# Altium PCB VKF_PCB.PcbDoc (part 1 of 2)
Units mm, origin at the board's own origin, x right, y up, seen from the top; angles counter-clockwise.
Board outline 125 x 80 mm, 4 copper layers (Top Layer, Mid-Layer 1, Mid-Layer 2, Bottom Layer), stack 1.633 mm thick; 104 components, 58 nets, 332 pads, 515 vias.
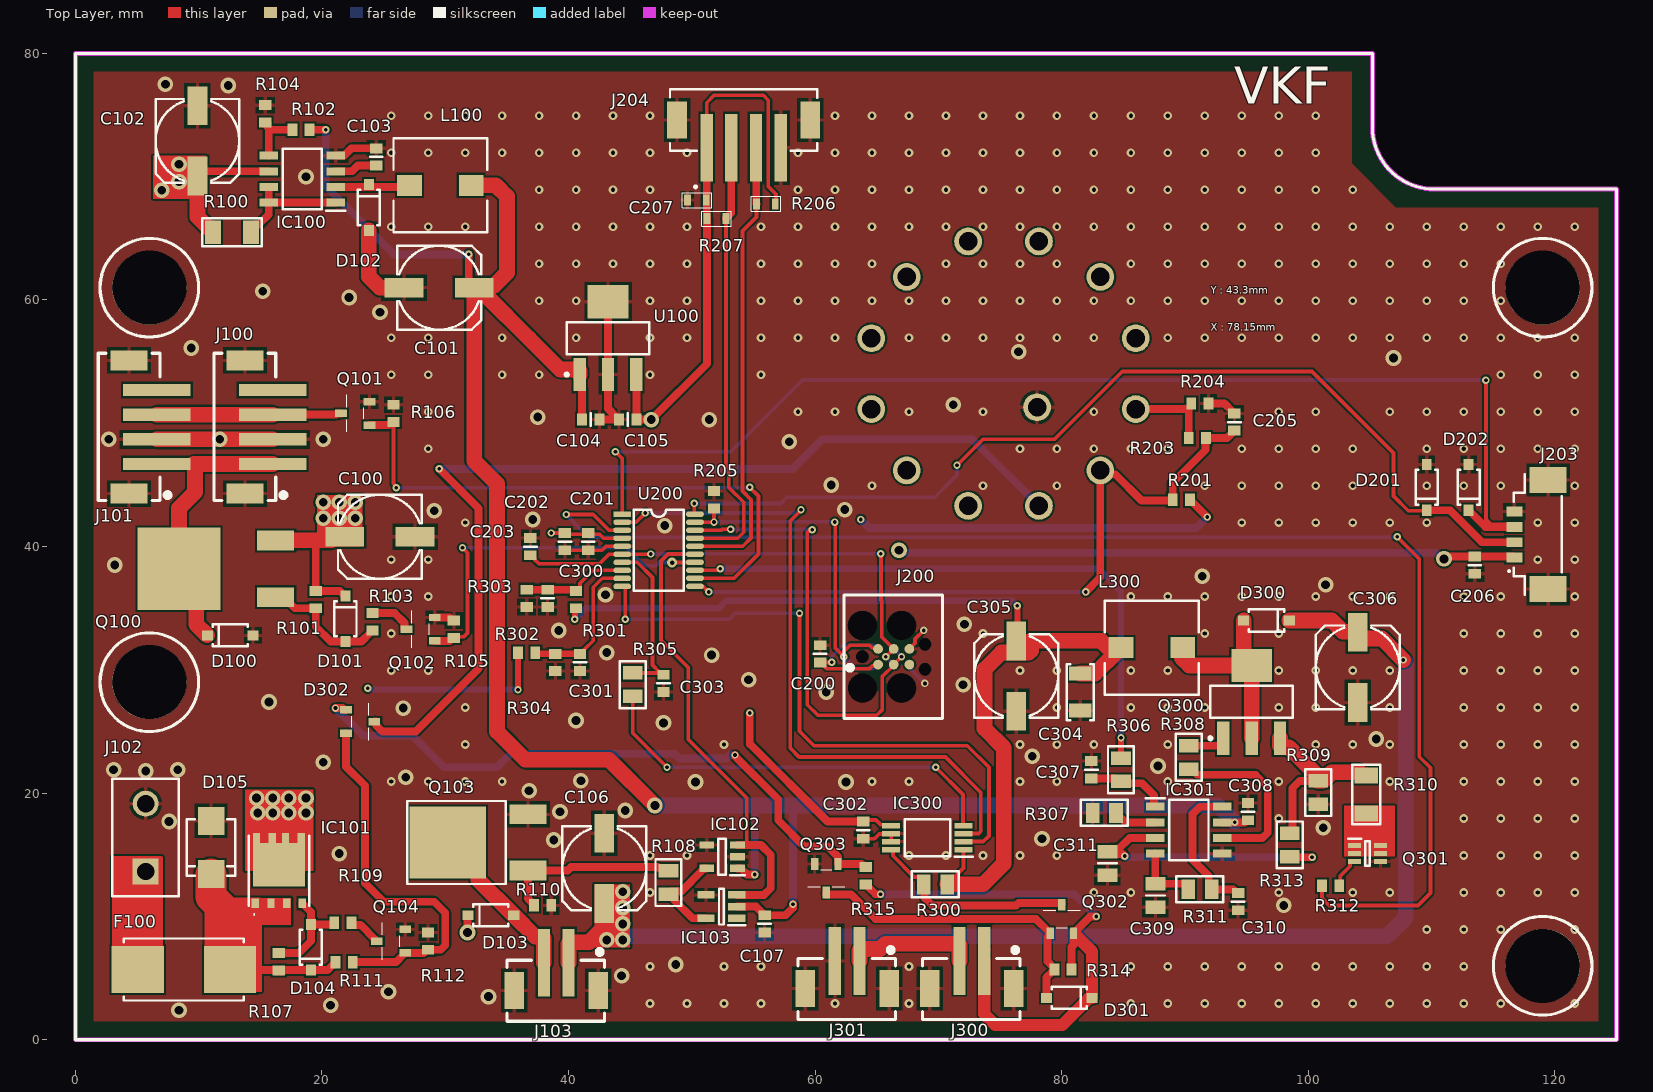
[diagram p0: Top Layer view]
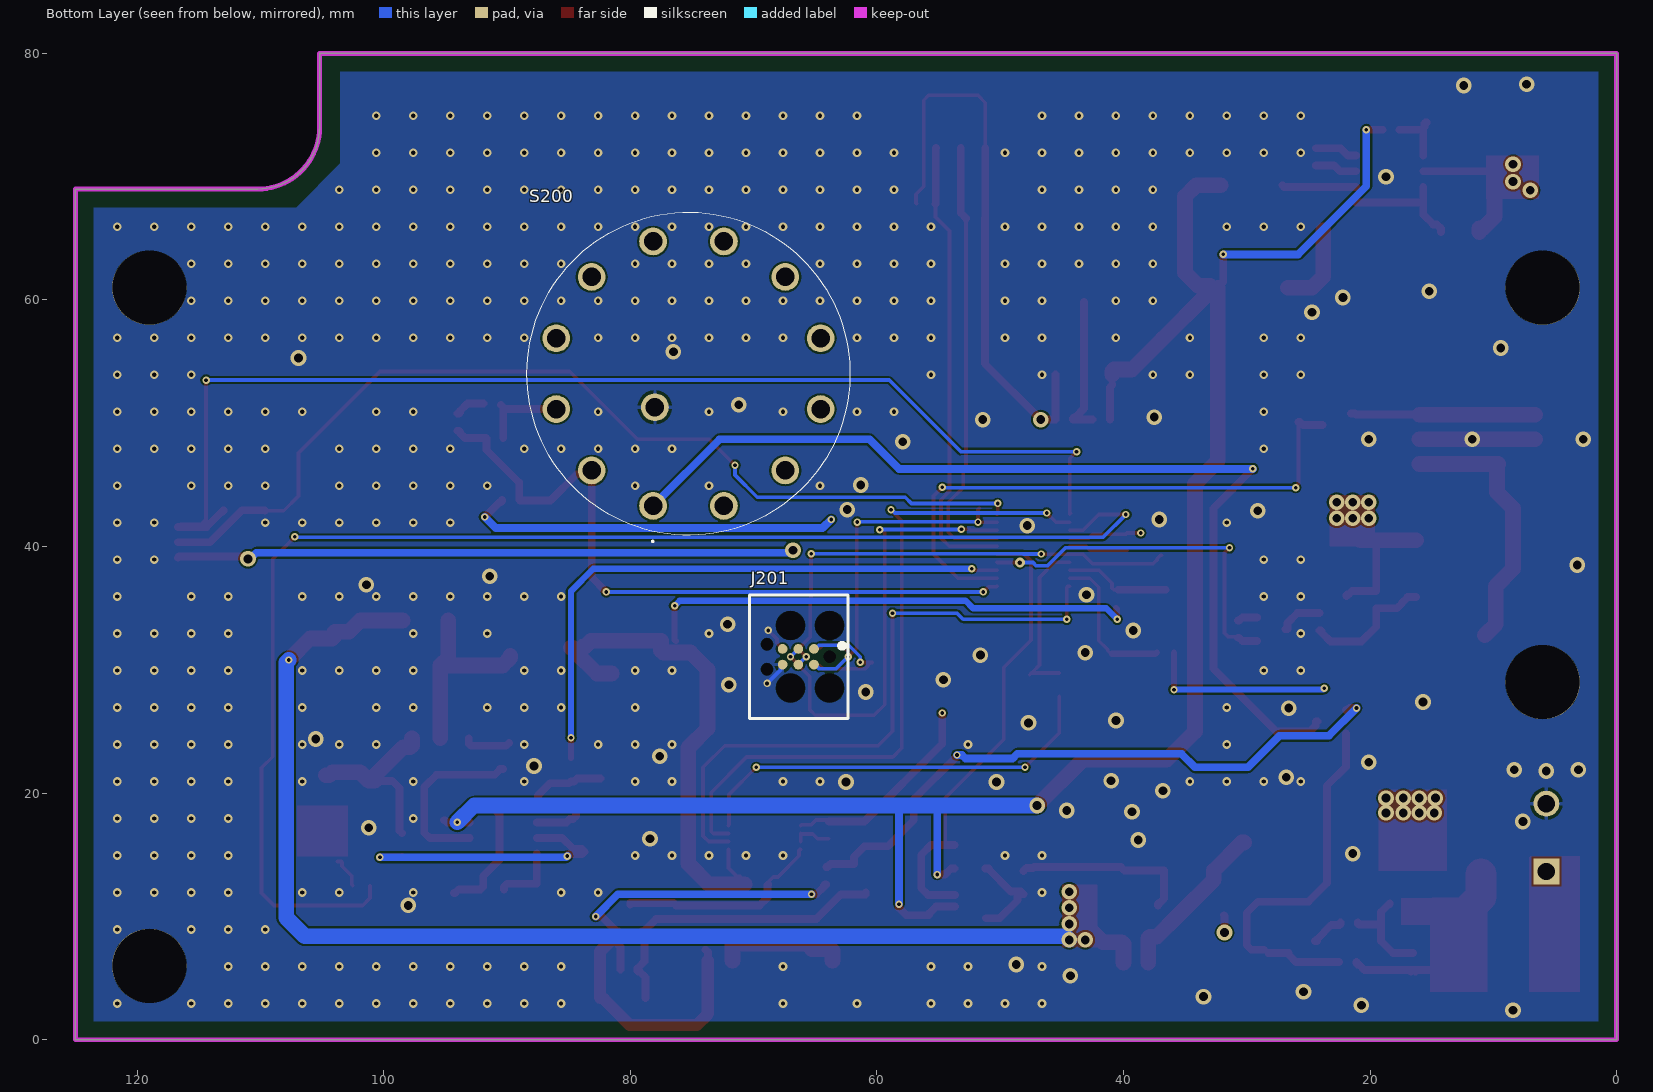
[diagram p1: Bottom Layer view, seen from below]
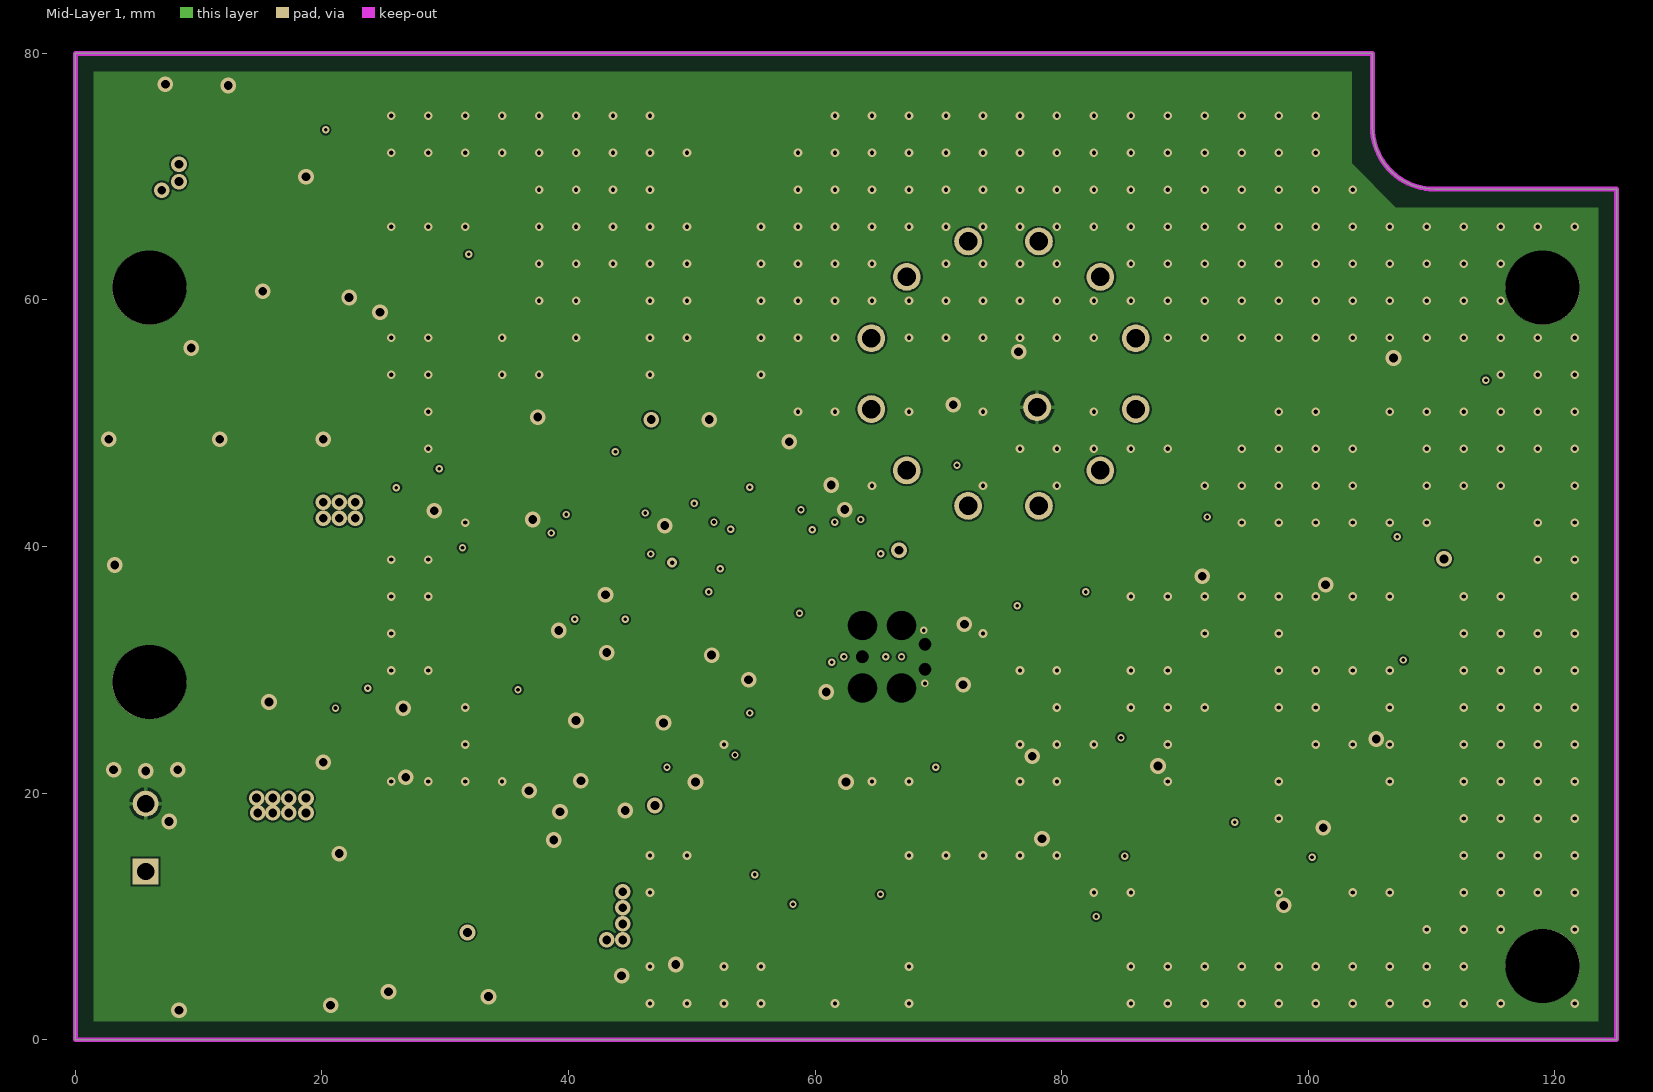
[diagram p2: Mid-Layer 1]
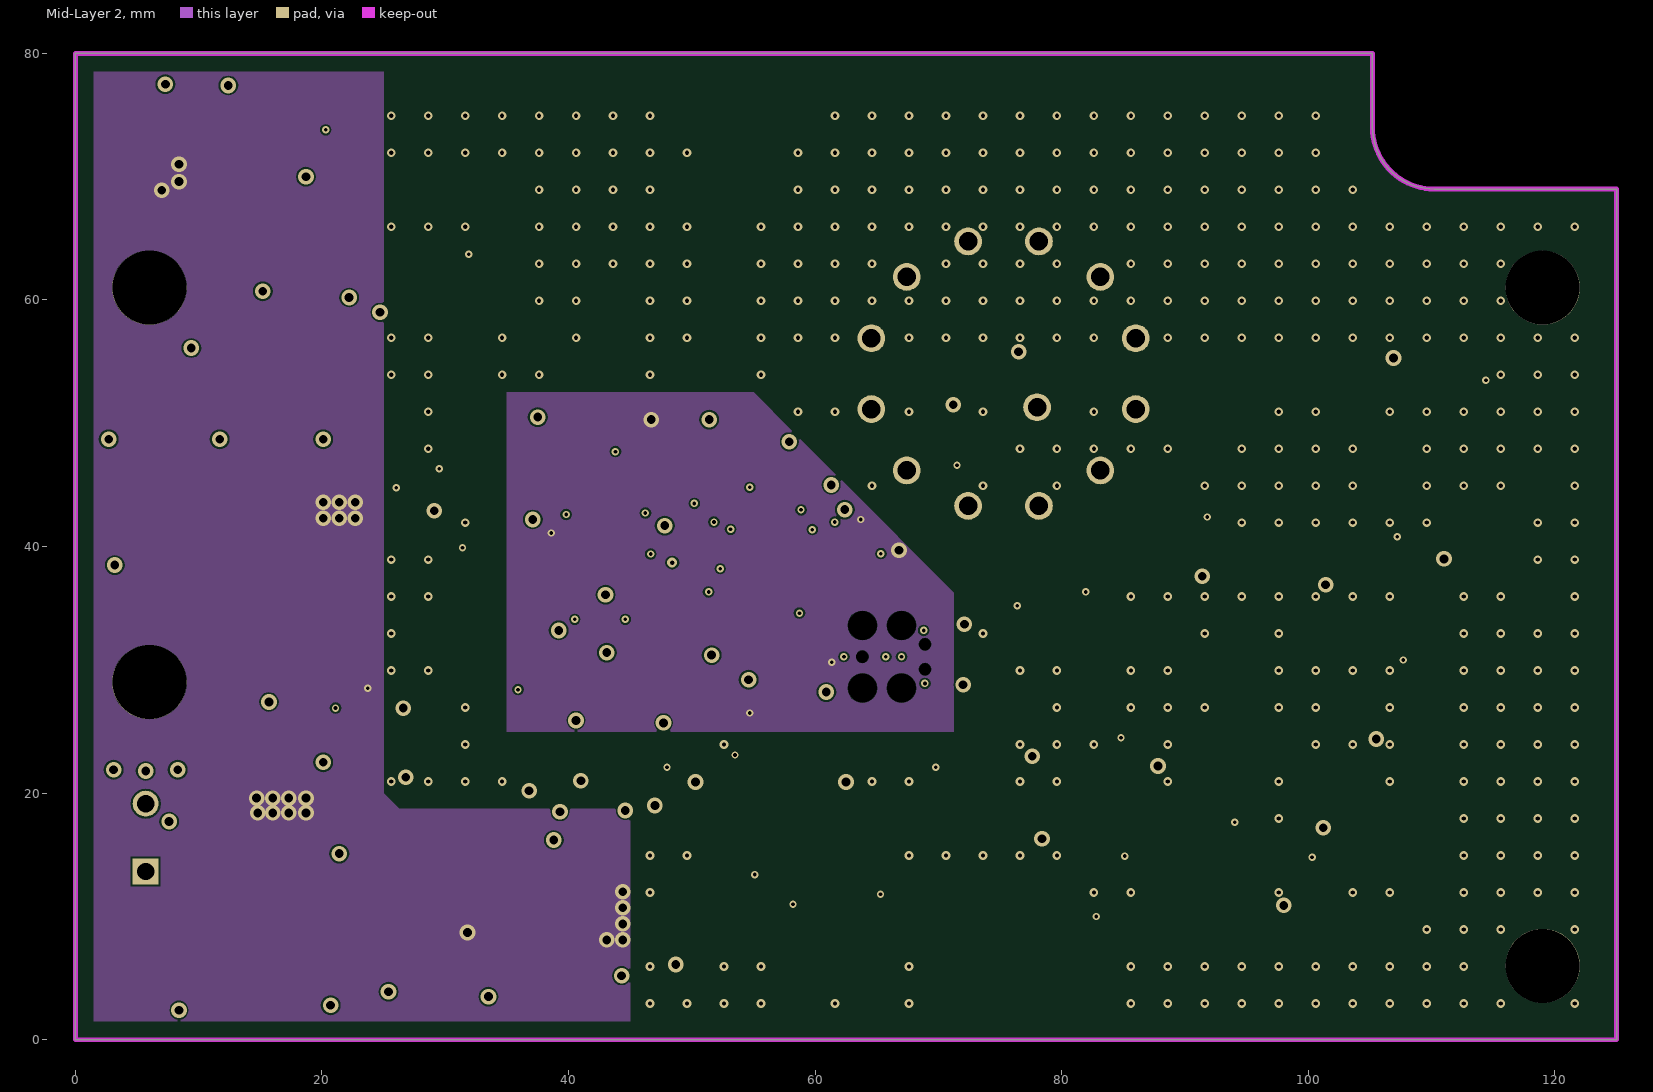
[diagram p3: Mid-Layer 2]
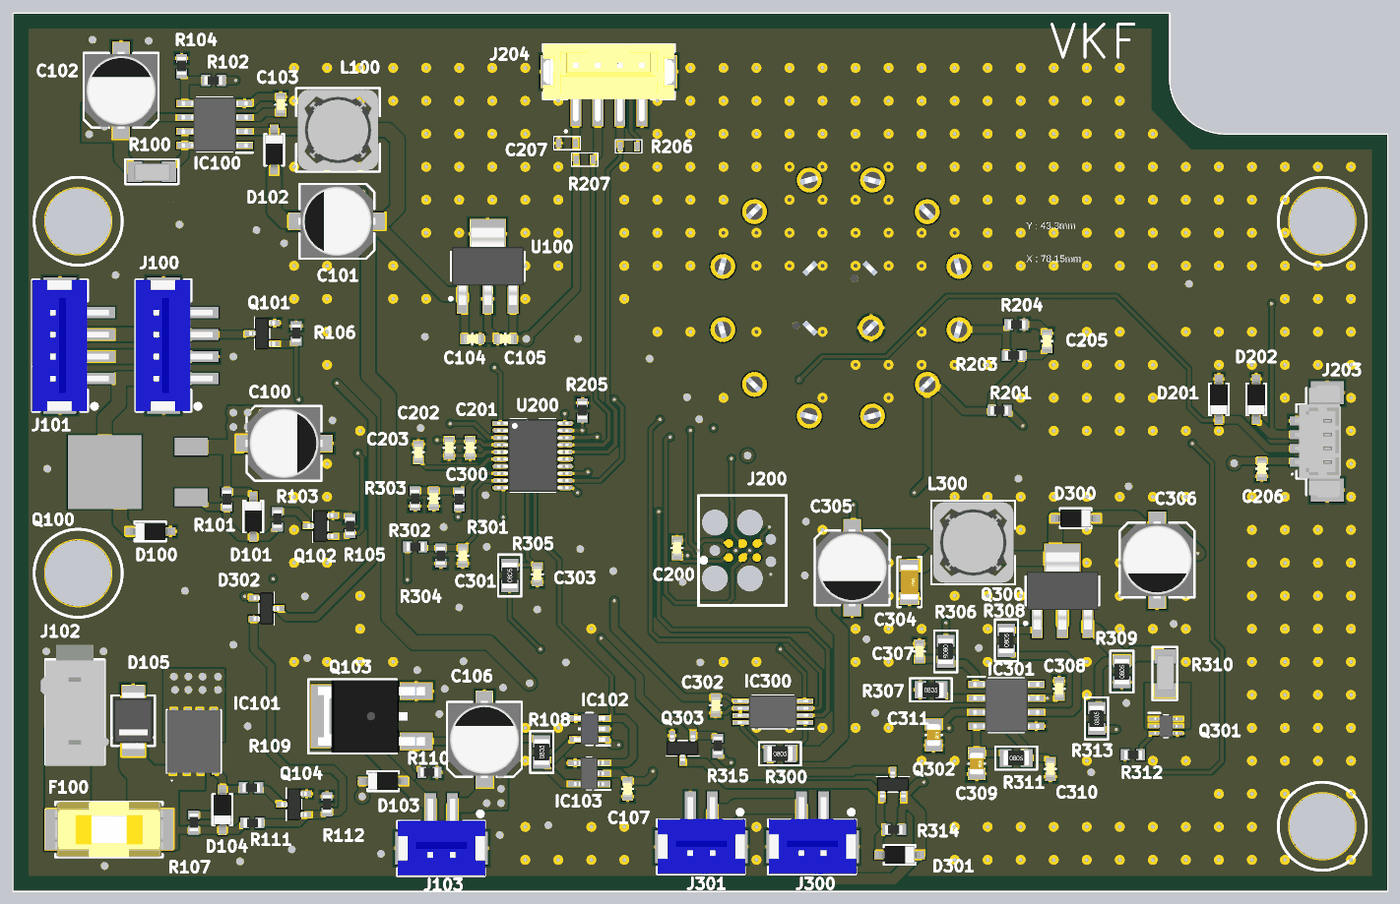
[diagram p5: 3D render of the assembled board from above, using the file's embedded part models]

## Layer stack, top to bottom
Top Solder: solder mask 0.001, Solder Resist, Dk 3.5
Top Layer: signal copper 0.035
Dielectric1: core 0.7, FR-4, Dk 4.8
Mid-Layer 1: signal copper 0.018
Dielectric 3: dielectric 0.127, Polyamide, Dk 3.2
Mid-Layer 2: signal copper 0.018
Dielectric2: core 0.7, FR-4, Dk 4.2
Bottom Layer: signal copper 0.035
Bottom Solder: solder mask 0.01, Solder Resist, Dk 3.5

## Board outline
0,0 125,0 125,69 110.2,69 cw(c110.2,74) 105.2,74 105.2,80 0,80

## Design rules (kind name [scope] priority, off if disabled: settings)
Clearance Clearance_Trous_All [HasPad('Free-Trou' )] p1: gap=0.5 ignorepadtopadclearanceinfootprint=FALSE except(0: Arc-Hole Track-Hole SMDPad-Hole THPad-Hole Via-Hole Fill-Hole Poly-Hole Region-Hole Text-Hole)
Clearance Clearance_Via_Pads [IsVia vs IsPad] p2: gap=0.2 ignorepadtopadclearanceinfootprint=FALSE except(0: Arc-Hole Track-Hole SMDPad-Hole THPad-Hole Via-Hole Fill-Hole Poly-Hole Region-Hole Text-Hole; 0.3: Track-Poly SMDPad-Poly THPad-Poly Via-Poly Fill-Poly Poly-Poly)
Clearance Clearance_KOL_Pad [(IsTrack Or IsArc) And OnLayer('Keep-out Layer' ) vs IsPad] p3: gap=0.6 ignorepadtopadclearanceinfootprint=FALSE except(0: Arc-Hole Track-Hole SMDPad-Hole THPad-Hole Via-Hole Fill-Hole Poly-Hole Region-Hole Text-Hole)
Clearance Clearance_KOL_Via [(IsTrack Or IsArc) And OnLayer('Keep-out Layer' ) vs IsVia] p4: gap=0.25 ignorepadtopadclearanceinfootprint=FALSE except(0: Arc-Hole Track-Hole SMDPad-Hole THPad-Hole Via-Hole Fill-Hole Poly-Hole Region-Hole Text-Hole)
Clearance Clearance_KOL_All [(IsTrack Or IsArc) And OnLayer('Keep-out Layer' )] p5: gap=0.15 ignorepadtopadclearanceinfootprint=FALSE except(0: Arc-Hole Track-Hole SMDPad-Hole THPad-Hole Via-Hole Fill-Hole Poly-Hole Region-Hole Text-Hole)
Clearance Clearance_Fiduciales [HasPad('Free-f')] p6: gap=0.5 ignorepadtopadclearanceinfootprint=FALSE except(0: Arc-Hole Track-Hole SMDPad-Hole THPad-Hole Via-Hole Fill-Hole Poly-Hole Region-Hole Text-Hole)
Clearance Clearance_All_Power [All vs InNet('GND_MECA')] p7: gap=0.5 ignorepadtopadclearanceinfootprint=FALSE except(0: Arc-Hole Track-Hole SMDPad-Hole THPad-Hole Via-Hole Fill-Hole Poly-Hole Region-Hole Text-Hole)
Clearance "Clearance All" [All] p8: gap=0.15 ignorepadtopadclearanceinfootprint=FALSE except(0: Arc-Hole Track-Hole SMDPad-Hole THPad-Hole Via-Hole Fill-Hole Poly-Hole Region-Hole Text-Hole)
ComponentClearance [All] p1: gap=0.6 collisioncheckmode=3 verticalgap=0.254 showdistances=FALSE
DiffPairsRouting [All] p1: maxlimit=3 minlimit=0.15 mostfreqgap=0.2 substack1={CD9D98E9-E3DC-47B0-9C38-DEE56D303F75} toplayer_{cd9d98e9-e3dc-47b0-9c38-dee56d303f75}_minwidth=0.381 toplayer_{cd9d98e9-e3dc-47b0-9c38-dee56d303f75}_maxwidth=0.381 toplayer_{cd9d98e9-e3dc-47b0-9c38-dee56d303f75}_prefwidth=0.381 midlayer1_{cd9d98e9-e3dc-47b0-9c38-dee56d303f75}_minwidth=0.381 midlayer1_{cd9d98e9-e3dc-47b0-9c38-dee56d303f75}_maxwidth=0.381 midlayer1_{cd9d98e9-e3dc-47b0-9c38-dee56d303f75}_prefwidth=0.381 midlayer2_{cd9d98e9-e3dc-47b0-9c38-dee56d303f75}_minwidth=0.381 midlayer2_{cd9d98e9-e3dc-47b0-9c38-dee56d303f75}_maxwidth=0.381 midlayer2_{cd9d98e9-e3dc-47b0-9c38-dee56d303f75}_prefwidth=0.381 bottomlayer_{cd9d98e9-e3dc-47b0-9c38-dee56d303f75}_minwidth=0.381 bottomlayer_{cd9d98e9-e3dc-47b0-9c38-dee56d303f75}_maxwidth=0.381 bottomlayer_{cd9d98e9-e3dc-47b0-9c38-dee56d303f75}_prefwidth=0.381 toplayer_minwidth=0.381 toplayer_maxwidth=0.381 toplayer_prefwidth=0.381 midlayer1_minwidth=0.381 midlayer1_maxwidth=0.381 midlayer1_prefwidth=0.381 midlayer2_minwidth=0.381 midlayer2_maxwidth=0.381 midlayer2_prefwidth=0.381 bottomlayer_minwidth=0.381 bottomlayer_maxwidth=0.381 bottomlayer_prefwidth=0.381 substack2={AC1A69B8-2080-43DA-BC4E-ABC400F5E514} toplayer_{ac1a69b8-2080-43da-bc4e-abc400f5e514}_minwidth=0.381 toplayer_{ac1a69b8-2080-43da-bc4e-abc400f5e514}_maxwidth=0.381 toplayer_{ac1a69b8-2080-43da-bc4e-abc400f5e514}_prefwidth=0.381 midlayer1_{ac1a69b8-2080-43da-bc4e-abc400f5e514}_minwidth=0.381 midlayer1_{ac1a69b8-2080-43da-bc4e-abc400f5e514}_maxwidth=0.381 midlayer1_{ac1a69b8-2080-43da-bc4e-abc400f5e514}_prefwidth=0.381 midlayer2_{ac1a69b8-2080-43da-bc4e-abc400f5e514}_minwidth=0.381 midlayer2_{ac1a69b8-2080-43da-bc4e-abc400f5e514}_maxwidth=0.381 midlayer2_{ac1a69b8-2080-43da-bc4e-abc400f5e514}_prefwidth=0.381 bottomlayer_{ac1a69b8-2080-43da-bc4e-abc400f5e514}_minwidth=0.381 bottomlayer_{ac1a69b8-2080-43da-bc4e-abc400f5e514}_maxwidth=0.381 bottomlayer_{ac1a69b8-2080-43da-bc4e-abc400f5e514}_prefwidth=0.381 maxuncoupledlength=12.7
FabricationTestPointUsage [All] p1: valid=0 allowmultiple=TRUE
FabricationTestpoint [All] p1: side=3 testpointundercomponent=TRUE minsize=1 maxsize=4 preferedsize=1 minholesize=0 maxholesize=2 preferedholesize=0.4 testpointgrid=0.025 allowsidetop=TRUE allowsidebottom=TRUE usegrid=FALSE gridtolerance=0
Height [All] p1: minheight=0 maxheight=50 prefheight=12.7
HoleSize [All] p1: absolutevalues=TRUE maxlimit=8 minlimit=0.3 maxpercent=80.000 minpercent=20.000
MinimumAnnularRing [IsPad] p1: minimumring=0.15
MinimumAnnularRing MinimumAnnularRing_Via [IsVia] p2: minimumring=0.15
MinimumSolderMaskSliver [All] p1: minsoldermaskwidth=0
PasteMaskExpansion [All] p1: expansion=-0.05
PlaneClearance [All] p1: clearance=0.5
PlaneConnect [All] p1: planeconnectstyle=Relief reliefexpansion=0.3 reliefentries=4 reliefconductorwidth=0.3 reliefairgap=0.3
PolygonConnect "PolygonConnect_Free Trous" [HasPad('Free-Trou' )] p1: connectstyle=Direct reliefconductorwidth=0.254 reliefentries=4 polygonreliefangle="90 Angle" airgapwidth=0.254
PolygonConnect PolygonConnect_Vias [IsVia] p2: connectstyle=Direct reliefconductorwidth=0.254 reliefentries=4 polygonreliefangle="90 Angle" airgapwidth=0.254
PolygonConnect PolygonConnect_Power [InNet('GND_MECA') Or InNet('VBAT')] p3: connectstyle=Relief reliefconductorwidth=1 reliefentries=4 polygonreliefangle="90 Angle" airgapwidth=0.254
PolygonConnect PolygonConnect_Power_1 [InNet('GND_MECA') Or InNet('VBAT')] p4 off: connectstyle=Relief reliefconductorwidth=0.5 reliefentries=4 polygonreliefangle="90 Angle" airgapwidth=0.254
PolygonConnect PolygonConnect_GND [InNet('GND')] p5: connectstyle=Relief reliefconductorwidth=0.3 reliefentries=4 polygonreliefangle="90 Angle" airgapwidth=0.254
PolygonConnect PolygonConnect_GND_1 [InNet('GND')] p6 off: connectstyle=Relief reliefconductorwidth=0.3 reliefentries=4 polygonreliefangle="90 Angle" airgapwidth=0.254
PolygonConnect PolygonConnect_All [All] p7: connectstyle=Relief reliefconductorwidth=0.3 reliefentries=4 polygonreliefangle="90 Angle" airgapwidth=0.254
RoutingCorners [All] p1: cornerstyle=45-Degree minsetback=1 maxsetback=3
RoutingVias [All] p1: holewidth=0.35 width=0.8 viastyle="Through Hole" minholewidth=0.3 minwidth=0.6 maxholewidth=1.5 maxwidth=2.8
SilkToSilkClearance [All] p1 off: silktosilkclearance=0.6
SilkToSolderMaskClearance SilkscreenOverComponentPads [IsPad] p1 off: minsilkscreentomaskgap=0 clearancetoexposedcopper=TRUE
SolderMaskExpansion SolderMaskExpansion_Via [(IsVia)] p1: expansion=0 istentingtop=FALSE
SolderMaskExpansion [All] p2: expansion=0.1 istentingtop=FALSE
Width Alim [InNet('15V') Or InNet('15V1') Or InNet('15V2') Or InNet('5V') Or InNet('5V1') Or InNet('5V2') Or InNet('GND') Or InNet('3.3V') Or InNet('12V')] p1: maxlimit=5 minlimit=0.15 preferedwidth=0.3 substack1={CD9D98E9-E3DC-47B0-9C38-DEE56D303F75} substack2={AC1A69B8-2080-43DA-BC4E-ABC400F5E514}
Width Power [InNet('GND_MECA') Or InNet('VBAT')] p2: maxlimit=5 minlimit=0.15 preferedwidth=1.5 substack1={CD9D98E9-E3DC-47B0-9C38-DEE56D303F75} substack2={AC1A69B8-2080-43DA-BC4E-ABC400F5E514}
Width All [All] p3: maxlimit=3 minlimit=0.15 preferedwidth=0.2 substack1={CD9D98E9-E3DC-47B0-9C38-DEE56D303F75} substack2={AC1A69B8-2080-43DA-BC4E-ABC400F5E514}
17 further rules are at their usual default settings.

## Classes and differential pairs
component class VKF_SOLAIRE: C300 C301 C302 C303 C304 C305 C306 C307 C308 C309 C310 C311 D300 D301 D302 IC300 IC301 J300 J301 L300 Q300 Q301 Q302 Q303 R300 R301 R302 R303 R304 R305 R306 R307 R308 R309 R310 R311 R312 R313 R314 R315
component class VKF_ALIM: C100 C101 C102 C103 C104 C105 C106 C107 D100 D101 D102 D103 D104 D105 F100 IC100 IC101 IC102 IC103 J100 J101 J102 J103 L100 Q100 Q101 Q102 Q103 Q104 R100 R101 R102 R103 R104 R105 R106 R107 R108 R109 R110 R111 R112 U100
component class VKF_CPU: C200 C201 C202 C203 C205 C206 C207 D201 D202 J200 J201 J203 J204 R201 R203 R204 R205 R206 R207 S200 U200

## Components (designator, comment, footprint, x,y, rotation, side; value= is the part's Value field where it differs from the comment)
C100 "100µF" CP_D8 24.7,40.8 r0 top
C101 "220µF" CP_D8 29.5,61 r180 top
C102 "100µF" CP_D8 9.9,72.9 r90 top
C103 "470pF" CAP0603 24.4,71.6 r90 top
C104 "1µF" CAP0603 41.8,50.3 r0 top
C105 "2.2µF" CAP0603 44.8,50.3 r180 top
C106 "100µF" CP_D8 42.9,13.9 r90 top
C107 "100nF" CAP0603 55.9,9.4 r270 top
C200 "100nF" CAP0603 60.4,31.3 r90 top
C201 "100nF" CAP0603 41.6,40.4 r270 top
C202 "1µF" CAP0603 39.7,40.4 r270 top
C203 "100nF" CAP0603 36.9,40 r90 top
C205 "100nF" CAP0603 94,50.1 r90 top
C206 "100nF" CAP0603 113.5,38.5 r270 top
C207 "10µF" CAP_0603_0H80 50.4,68.1 r0 top
C300 "100nF" CAP0603 38.3,35.8 r270 top
C301 "100nF" CAP0603 40.93,30.6 r270 top
C302 "100nF" CAP0603 63.9,17 r270 top
C303 "100nF" CAP0603 47.7,28.9 r270 top
C304 "10µF" CAP1206 81.5,28.2 r270 top
C305 "100µF" CP_D8 76.3,29.5 r270 top
C306 "100µF" CP_D8 104,30.2 r270 top
C307 "1µF" CAP0603 82.4,21.9 r90 top
C308 "100nF" CAP0603 95.1,18.5 r90 top
C309 "1nF" CAP0805 87.6,11.7 r270 top
C310 "100nF" CAP0603 94.3,11.2 r270 top
C311 "1nF" CAP0805 83.7,14.3 r270 top
D100 "RB160M-40TR" SOD-123 12.55,32.8 r0 top
D101 "MMSZ5242BT1G" SOD-123 21.9,34.15 r270 top
D102 "RB160M-40TR" SOD-123 23.8,67.5 r270 top
D103 "RB160M-40TR" SOD-123 33.7,10.1 r0 top
D104 "MMSZ5242BT1G" SOD-123 19.1,7.5 r90 top
D105 "P6SMB27AT3" SMB 11,15.6 r90 top
D201 "PTVS3V3S1UR" SOD-123 109.6,44.8 r90 top
D202 "PTVS3V3S1UR" SOD-123 113,44.8 r90 top
D300 "RB160M-40TR" SOD-123 96.6,34 r180 top
D301 "MMSZ5242BT1G" SOD-123 80.6,3.4 r180 top
D302 "BAT54C,215" SOT23 23.1,25.8 r270 top
F100 "0154007.DRT" 0154 8.8,5.7 r0 top
IC100 "MC33063AD" SOIC127P600X175-8N 18.4,69.8 r180 top
IC101 "RS1G201ATTB1" RS1G201ATTB1 16.5,13.715 r0 top
IC102 "FAN3111CSX_NC" SOT95P280X145-5N 52.45,14.85 r180 top
IC103 "MCP1416T-E_OT" SOT95P270X145-5N 52.4,10.8 r180 top
IC300 "CS70P" SOP65P640X120-8N 69.1,16.4 r180 top
IC301 "UCC28C43D" SOIC127P600X175-8N 90.3,17 r0 top
J100 "B4B-PH-SM4-TB" "CNT-S (JST Ref B4B-PH-SM4)" 16,48.7 r90 top
J101 "B4B-PH-SM4-TB" "CNT-S (JST Ref B4B-PH-SM4)" 6.6,48.7 r90 top
J102 "39-28-1023" "CNT-T (MOLEX Ref 39-31-0020)" 5.7,16.4 r180 top
J103 "B2B-PH-SM4-TB" "CNT-S (JST Ref B2B-PH-SM4)" 38,6.25 r180 top
J200 "TC2030" TC2030-IDC-FP 63.83,31.065 r0 top
J201 "TC2030" TC2030-IDC-FP 63.83,31.065 r0 bottom
J203 "53398-0471" "CNT-S (MOLEX Ref SD-53398-0471)" 116.7,39.1 r90 top
J204 "B4B-PH-SM4-TB_LF__SN_" B4B-PH-SM4_1 54.2,77.1 r0 top
J300 "B2B-PH-SM4-TB" "CNT-S (JST Ref B2B-PH-SM4)" 71.7,6.4 r180 top
J301 "B2B-PH-SM4-TB" "CNT-S (JST Ref B2B-PH-SM4)" 61.6,6.4 r180 top
L100 "330.0 µH" WE-PD-M-PB 29.6,69.3 r180 top
L300 "330.0 µH" WE-PD-M-PB 87.3,31.8 r180 top
Q100 "DMP4051LK3" DPAK 16.25,38.2 r90 top
Q101 "2N7002F" SOT23 22.7,50.8 r90 top
Q102 "2N7002F" SOT23 28,33.3 r90 top
Q103 "DMP6180SK3Q-13" TO-252_DPAK_3P 32.2,16 r90 top
Q104 "2N7002F" SOT23 25.6,8 r90 top
Q300 "BSP318SH6327XTSA1" ONSC-SOT-223-4-318E-04_V 95.4,27.4 r90 top
Q301 "SI1442DH-T1-BE3" SOT65P210X110-6N 104.8,15.1 r0 top
Q302 "NTR3A052PZT1G" SOT23 80,9.8 r0 top
Q303 "2N7002F" SOT23 60.9,13.1 r180 top
R100 "0.68" RES1206 12.7,65.5 r0 top
R101 "10k" RES0603 19.5,35.7 r270 top
R102 "10k" RES0603 18.3,73.8 r0 top
R103 "10k" RES0603 24.1,33.9 r270 top
R104 "1k2" RES0603 15.4,75.1 r270 top
R105 "10k" RES0603 30.7,33.3 r90 top
R106 "10k" RES0603 25.8,50.8 r270 top
R107 "100k" RES0603 16.5,6.326 r270 top
R108 "22R" RES0805 48.1,12.75 r90 top
R109 "100k" RES0603 21.7,9.5 r180 top
R110 "10k" RES0603 37.9,10.9 r0 top
R111 "1M" RES0603 21.8,6.3 r180 top
R112 "100k" RES0603 28.6,8 r270 top
R201 "100k" RES0603 89.7,43.8 r0 top
R203 "100k" RES0603 91,48.8 r0 top
R204 "100k" RES0603 91.2,51.6 r180 top
R205 "100k" RES0603 51.8,43.8 r270 top
R206 "10K" RES_0603_0H90 56,67.8 r0 top
R207 "10K" RES_0603_0H90 52,66.6 r180 top
R300 "0R1" RES0805 69.75,12.6 r0 top
R301 "33k" RES0603 40.6,35.7 r270 top
R302 "100k" RES0603 36.6,31.4 r180 top
R303 "10k" RES0603 36.6,35.8 r90 top
R304 "10k" RES0603 38.93,30.6 r90 top
R305 "1k" RES0805 45.2,28.8 r90 top
R306 "10k" RES0805 84.8,21.9 r270 top
R307 "1k" RES0805 83.45,18.4 r0 top
R308 "22R" RES0805 90.3,22.9 r90 top
R309 "3R3" RES0805 100.8,20.05 r90 top
R310 "0.68" RES1206 104.7,19.9 r90 top
R311 "10k" RES0805 91.2,12.2 r0 top
R312 "10k" RES0603 101.8,12.5 r180 top
R313 "1k" RES0805 98.5,15.8 r90 top
R314 "100k" RES0603 80.1,5.7 r0 top
R315 "100k" RES0603 64.1,13.3 r270 top
S200 "CK1049" CK1059 78.15,43.3 r180 bottom locked
U100 "UA78M33CDCY" SOT223_MOSFET 43.2,56.9 r90 top value=UA78M33
U200 "STM32G030F6P6" TSSOP20-0.65 47.3,39.7 r0 top

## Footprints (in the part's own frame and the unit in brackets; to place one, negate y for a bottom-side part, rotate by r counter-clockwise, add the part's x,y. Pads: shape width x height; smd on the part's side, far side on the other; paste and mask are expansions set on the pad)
0154 [mm] "Fusible série 0154"
  rect 4.24x3.81 smd paste-0.05 mask+0.1: 1(-3.745,0) 2(3.745,0)
  silkscreen extent -4.86,-2.51 4.86,2.51, body extent -4.92,-2.51 4.91,2.51, height 3.81
B4B-PH-SM4_1 [mm]
  rect 1x5.5 smd: 1(-3,-4.75) 2(-1,-4.75) 3(1,-4.75) 4(3,-4.75)
  rect 1.6x3 smd: MP1(-5.4,-2.5) MP2(5.4,-2.5)
  silkscreen extent -5.97,-8.02 5.97,0, body extent -5.98,-7.03 5.97,-0.03, height 6.8
CAP0603 [mm]
  rect 0.8x1 smd mask+0.075: 1(-0.7,0) 2(0.7,0)
  silkscreen extent 0,-0.5 0,0.5, body extent -0.8,-0.41 0.8,0.41, height 0.57
CAP0805 [mm]
  rect 1.1x1.6 smd mask+0.075: 1(-0.95,0) 2(0.95,0)
  silkscreen extent 0,-0.75 0,0.75, body extent -1,-0.62 1,0.63, height 0.78
CAP1206 [mm] "Condensateur 1206"
  rect 1.15x1.8 smd paste-0.05 mask+0.1: 1(-1.5,0) 2(1.5,0)
  silkscreen extent -2.27,-1.1 2.27,1.1, body extent -1.6,-0.8 1.6,0.8, height 1
CAP_0603_0H80 [mil] "refusion"
  rect 22x35 smd: 1(-30,0) 2(30,0)
  silkscreen extent -47,-24 47,24, body extent -31,-16 31,16, height 31
CK1059 [mm]
  round 2.25 hole 1.5: 1(0,0) 2(-4.976,2.873) 3(-7.849,7.849) 4(-7.849,13.595) 5(-4.976,18.571) 6(0,21.444) 7(5.746,21.444) 8(10.722,18.571) 9(13.595,13.595) 10(13.595,7.849) 11(10.722,2.873) 12(5.746,0) A1(0.151,7.999)
  silkscreen extent -10.23,-2.94 15.97,23.82, body extent -10.15,-2.4 16.05,23.8, height 42.2
"CNT-S (JST Ref B2B-PH-SM4)" [mm]
  rect 1x5.5 smd paste+0 mask+0.075: 1(-2,0) 2(0,0)
  rect 1.6x3 smd paste+0 mask+0.075: 3(-4.4,2.25) 4(2.4,2.25)
  silkscreen extent -4.9,-1.08 3,4.75, body extent -4.97,-2.25 2.98,4.75, height 6.6
"CNT-S (JST Ref B4B-PH-SM4)" [mm]
  rect 1x5.5 smd paste+0 mask+0.075: 1(-2,0) 2(0,0) 3(2,0) 4(4,0)
  rect 1.6x3 smd paste+0 mask+0.075: 5(-4.4,2.25) 6(6.4,2.25)
  silkscreen extent -4.97,-1.08 6.98,4.75, body extent -4.97,-2.2 6.98,4.8, height 6.6
"CNT-S (MOLEX Ref SD-53398-0471)" [mm]
  rect 0.8x1.3 smd paste+0 mask+0.075: 1(0,0) 2(1.25,0) 3(2.5,0) 4(3.75,0)
  rect 2.1x3 smd paste+0 mask+0.075: 5(-2.55,-2.75) 6(6.3,-2.75)
  silkscreen extent -3,-3.85 6.75,0.56, body extent -3.2,-3.9 6.95,0.3, height 4.7
"CNT-T (MOLEX Ref 39-31-0020)" [mm]
  rect 2.1x2.1 hole 1.4 paste-2539.97 mask+0.075: 1(0,2.75)
  round 2.1 hole 1.4 paste-2539.97 mask+0.075: 2(0,-2.75)
  silkscreen extent -2.7,-4.77 2.7,4.77, body extent -3.1,-6.07 3.1,4.93, height 12.8
CP_D8 [mm] "Condensateur Polarisé Boîtier D8"
  rect 3.15x1.6 smd paste-0.05 mask+0.1: 1(-2.85,0) 2(2.85,0)
  silkscreen extent -3.4,-3.4 3.4,3.4, body extent -3.5,-3.3 3.5,3.3, height 7.71
DPAK [mm]
  rect 1.6x3 smd paste+0 mask+0.075: 1(-2.3,0) 3(2.3,0)
  rect 6.7x6.7 smd paste+0 mask+0.075: 2(0,7.85)
  body extent -3.3,2.25 3.3,8.45, height 2.4
ONSC-SOT-223-4-318E-04_V [mm] "SOT223, 4-Leads, Body 6.5x3.5mm, Pitch 2.3mm, Lead Span 7mm, IPC Low Density"
  rect 2.7x1 smd: 1(-2.95,2.3) 2(-2.95,0) 3(-2.95,-2.3)
  rect 2.7x3.3 smd: 4(2.95,0)
  silkscreen extent -3.07,-3.35 1.3,3.47, body extent -3.5,-3.25 3.5,3.25, height 1.64
RES0603 [mm]
  rect 0.8x1 smd paste+0 mask+0.075: 1(-0.7,0) 2(0.7,0)
  body extent -0.82,-0.4 0.78,0.4, height 0.4
RES0805 [mm]
  rect 1.1x1.6 smd paste+0 mask+0.075: 1(-0.95,0) 2(0.95,0)
  silkscreen extent -1.9,-1.05 1.9,1.05, body extent -1.15,-0.67 1.15,0.68, height 0.76
RES1206 [mm]
  rect 1.3x1.9 smd paste+0 mask+0.075: 1(-1.55,0) 2(1.55,0)
  silkscreen extent -2.43,-1.12 2.4,1.12, body extent -1.58,-0.85 1.62,0.75, height 1
RES_0603_0H90 [mil]
  rect 22x35 smd: 1(-30,0) 2(30,0)
  silkscreen extent -47,-24 47,24, body extent -31,-16 31,16, height 35
RS1G201ATTB1 [mm]
  rect 0.59x0.8 smd: 1(-1.905,-2.645) 2(0.635,-2.645) 3(-0.635,-2.645) 4(1.905,-2.645)
  rect 0.59x0.82 smd: 5(1.81,2.645) 6(0.54,2.645) 7(-0.54,2.645) 8(-1.81,2.645)
  rect 4.21x3.5 smd: 9(0,0.485)
  silkscreen extent -2.45,-3.6 2.45,2.85, body extent -2.45,-2.85 2.45,2.85, height 1.2
SMB [mm] "Boîtier SMB"
  rect 2.25x2.15 smd paste-0.05 mask+0.1: 1(-2.15,0) 2(2.15,0)
  silkscreen extent -2.28,-1.97 2.28,1.97, body extent -2.65,-1.8 2.65,1.8, height 2.43
SOD-123 [mm] "Boîtier SOD-123"
  rect 0.9x0.8 smd paste-0.05 mask+0.1: 1(-1.85,0) 2(1.85,0)
  silkscreen extent -1.43,-0.9 1.43,0.9, body extent -1.85,-0.8 1.85,0.8, height 1.27
SOIC127P600X175-8N [mm]
  rect 1.525x0.65 smd: 1(-2.712,1.905) 2(-2.712,0.635) 3(-2.712,-0.635) 4(-2.712,-1.905) 5(2.712,-1.905) 6(2.712,-0.635) 7(2.712,0.635) 8(2.712,1.905)
  silkscreen extent -3.47,-2.45 1.6,2.58, body extent -3,-2.45 3,2.45, height 1.75
SOP65P640X120-8N [mm]
  rect 1.475x0.45 smd: 1(-2.938,0.975) 2(-2.938,0.325) 3(-2.938,-0.325) 4(-2.938,-0.975) 5(2.938,-0.975) 6(2.938,-0.325) 7(2.938,0.325) 8(2.938,0.975)
  silkscreen extent -3.67,-1.5 1.85,1.55, body extent -3.2,-1.5 3.2,1.5, height 1.2
SOT23 [mm] "Boîtier SOT23"
  rect 0.6x0.95 smd paste-0.05 mask+0.1: 1(-0.95,-1.15) 2(0.95,-1.15) 3(0,1.15)
  silkscreen extent -1.5,-0.7 1.5,0.7, body extent -1.46,-1.17 1.46,1.17, height 1
SOT65P210X110-6N [mm]
  rect 1.05x0.4 smd: 1(-1.05,0.65) 2(-1.05,0) 3(-1.05,-0.65) 4(1.05,-0.65) 5(1.05,0) 6(1.05,0.65)
  silkscreen extent -1.58,-1 0.18,1.2, body extent -1.05,-1 1.05,1, height 1.1
SOT95P270X145-5N [mm]
  rect 1.4x0.6 smd: 1(-1.25,0.95) 2(-1.25,0) 3(-1.25,-0.95) 4(1.25,-0.95) 5(1.25,0.95)
  silkscreen extent -1.95,-1.45 0.2,1.5, body extent -1.35,-1.45 1.35,1.45, height 1.45
SOT95P280X145-5N [mm]
  rect 1.2x0.6 smd: 1(-1.25,0.95) 2(-1.25,0) 3(-1.25,-0.95) 4(1.25,-0.95) 5(1.25,0.95)
  silkscreen extent -1.85,-1.45 0.3,1.5, body extent -1.4,-1.45 1.4,1.45, height 1.2
SOT223_MOSFET [mm] "SOT223, 4-Leads, Body 6.5x3.5mm, Pitch 2.3mm, Lead Span 7mm, IPC Low Density"
  rect 2.7x1 smd: 1(-2.95,2.3) 2(-2.95,0) 3(-2.95,-2.3)
  rect 2.7x3.3 smd: 2(2.95,0)
  silkscreen extent -3.07,-3.35 1.3,3.47, body extent -3.5,-3.25 3.5,3.25, height 1.64
TC2030-IDC-FP [mil] "Probe Sonde 6 pts no coponnent"
  round 60 hole 93.5 unplated paste-99999 mask-78.74: 0(0,-100) 0(0,100) 0(125,-100) 0(125,100)
  round 0 hole 39.37 unplated paste-99999 mask-39.37: 0(0,0) 0(200,-40) 0(200,40)
  round 30.98 smd paste-35.43 mask+2.95: 1(50,-25)
  round 30.98 smd paste-314.96 mask+2.95: 2(50,25)
  round 30.98 smd paste-31.5 mask+2.95: 3(100,-25) 4(100,25) 5(150,-25) 6(150,25)
  silkscreen extent -59,-197 256,197
TO-252_DPAK_3P [mm] "Boîtier TO-252_DPAK_3P"
  rect 1.6x3 smd paste-0.05 mask+0.1: 1(-2.28,-4.5) 3(2.28,-4.5)
  rect 5.8x6.2 smd paste-0.05 mask+0.1: 2(0,2)
  silkscreen extent -3.36,-2.72 3.36,5.3, body extent -3.29,-5.3 3.29,4.4, height 2.3
TSSOP20-0.65 [mm] "Boîtier TSSOP20, pas de 0.65 mm"
  rect 1.45x0.45 smd paste-0.05 mask+0.1: 1(-2.95,2.925)
  oval 1.45x0.45 smd paste-0.05 mask+0.1: 2(-2.95,2.275) 3(-2.95,1.625) 4(-2.95,0.975) 5(-2.95,0.325) 6(-2.95,-0.325) 7(-2.95,-0.975) 8(-2.95,-1.625) 9(-2.95,-2.275) 10(-2.95,-2.925) 11(2.95,-2.925) 12(2.95,-2.275) 13(2.95,-1.625) 14(2.95,-0.975) 15(2.95,-0.325) 16(2.95,0.325) 17(2.95,0.975) 18(2.95,1.625) 19(2.95,2.275) 20(2.95,2.925)
  silkscreen extent -2.02,-3.3 2.02,3.3, body extent -3.23,-3.3 3.23,3.3, height 1.35
WE-PD-M-PB [mm] "SMD Inductor, 2-Leads, Body 7.3x7.3x4.5 mm"
  rect 2x1.7 smd: 1(-2.5,0) 2(2.5,0)
  silkscreen extent -3.8,-3.8 3.8,3.8, body extent -3.65,-3.65 3.65,3.65, height 4.5

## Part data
C100 C102 C106 C305 C306: library part COND-EEEFPV101XAP, "Capacitor, ALU, 100µF, Case D, 20%, 35V", CASE="Case D", Dielectric=ALU, Voltage=35V
C101: library part COND-EEEFK1C221XP, "Capacitor, ALU, 220µF, Case D, 20%, 16V", CASE="Case D", Dielectric=ALU, Voltage=16V
C103: library part C0603-470pF-X7R-25V, "Capacitor, Ceramic, 470pF, 0603, 10%, 25V, X7R", CASE=0603, Dielectric=X7R, Voltage=25V
C104 C202 C307: library part C0603-1µF-X7R-16V, "Capacitor, Ceramic, 1µF, 0603, 10%, 16V, X7R", CASE=0603, Dielectric=X7R, Voltage=16V
C105: library part C0603-2.2µF-X7R-6.3V, "Capacitor, Ceramic, 2.2µF, 0603, 10%, 6.3V, X7R", CASE=0603, Dielectric=X7R, Voltage=6.3V
C107 C200 C201 C203 C205 C206 C300 C301 C302 C303 C308 C310: library part C0603-100nF-X7R-50V, "Capacitor, Ceramic, 100nF, 0603, 10%, 50V, X7R", CASE=0603, Dielectric=X7R, Voltage=50V
C207: library part capacitor
C304: library part C1206-10µF-X7R-35V, "Capacitor, Ceramic, 10µF, 1206, 10%, 35V, X7R", CASE=1206, Dielectric=X7R, Voltage=35V
C309 C311: library part C0805-1nF-X7R-50V, "Capacitor, Ceramic, 1nF, 0805, 10%, 50V, X7R", CASE=0805, Dielectric=X7R, Voltage=50V
D100 D102 D103 D300: "Diode Schottky, 1A, 40V, SOD-123", CASE=SOD-123
D101 D104 D301: "Zener, 12 V, 500 mW, SOD-123", CASE=SOD-123
D105: library part P6SMB27AT3_SMB, "Diode Transil Unidirectionnelle, série P6SMB27AT3, 27 V, SMB", CASE=SMB
D201 D202: "Diode TVS, série PTVS, 3.3 V, SOD-123", CASE=SOD-123
D302: "Dual schottky Diode Common Chatode 30V 200mA SOT23", CASE=SOT23
F100: "Surface Mount Fuses and holder. NANO 7A", CASE=NANO
IC100: "Integrated Circuit", Manufacturer_Name="Texas Instruments", Mouser Part Number=595-MC33063AD
IC101: "Integrated Circuit", Manufacturer_Name="ROHM Semiconductor"
IC102: library part FAN3111CSX, "Integrated Circuit", Manufacturer_Name="ON Semiconductor", Mouser Part Number=512-FAN3111CSX
IC103: "Integrated Circuit", Arrow Part Number=MCP1416T-E/OT, Manufacturer_Name=Microchip, Mouser Part Number=579-MCP1416T-E/OT
IC300: "Integrated Circuit", Manufacturer_Name=STMicroelectronics, Mouser Part Number=511-CS70P
IC301: "Integrated Circuit", Manufacturer_Name="Texas Instruments", Mouser Part Number=595-UCC28C43D
J100 J101: library part "CNT-JST-PH Series-SMT-4cts", "Connector PH JST Header,Top Entry, SMT, 5cts", CASE="PH series 4Cts"
J102: library part "CNT-MOLEX-Mini-Fit Jr-2cts", "Connector MOLEX Mini-Fit Jr, Top Entry, 2cts"
J103 J300 J301: library part "CNT-JST-PH Series-SMT-2cts", "Connector PH JST Header,Top Entry, SMT, 2cts", CASE="PH series 2Cts"
J200 J201: "Connector Sonde Probe, 6cts", CASE=TC2030-IDC
J203: library part CNT-MOLEX-PicoBlade-SMT-4cts, "Connector PicoBlade Header, SMT, 4cts", CASE="PicoBlade 4Cts"
J204: "Connector", Arrow Part Number=B4B-PH-SM4-TB(LF)(SN), Manufacturer_Name="JST (JAPAN SOLDERLESS TERMINALS)"
L100 L300: library part WURTH-330µH-0.40A-7.3x7.3_1, "SMD-Shielded Power Inductor WE-PD, L = 330.0 µH", CASE=WE-PD-M-PB
Q100: "Mosfet Canal P, 10A, 40V, DPAK", CASE=DPAK
Q101 Q102 Q104 Q303: "Transistor Mosfet 2N7002F, 385mA canal N, SOT23", CASE=SOT23
Q103: library part IPD135N03L, "Transistor Mosfet DMP6180SK3Q-13, canal N, TO-252_DPAK, 10A 60V", CASE=TO-252_DPAK
Q300: "Transistor Mosfet, 2.6A, 60V, canal N, Logic level, SOT223", CASE=SOT223
Q301: "Integrated Circuit", Manufacturer_Name=Vishay, Mouser Part Number=78-SI1442DH-T1-BE3
Q302: "Mosfet Canal P, 3A, 20V, SOT23", CASE=SOT23
R100 R310: library part R1206_0.68_1%, "Resistor, couche epaisse, 0.68, 1%, 500mW, 1206", CASE=1206, Power=500mW, Tolerance=1%
R101 R102 R103 R105 R106 R110 R303 R304 R312: library part R0603_10k_1%, "Resistor, Thin Film, 10k, 1%, 65mW, 0603", CASE=0603, Power=65mW, Tolerance=1%
R104: library part R0603_1k2_1%, "Resistor, Thin Film, 1k2, 1%, 65mW, 0603", CASE=0603, Power=65mW, Tolerance=1%
R107 R109 R112 R201 R203 R204 R205 R302 R314 R315: library part R0603_100k_1%_1, "Resistor, Thin Film, 100k, 1%, 65mW, 0603", CASE=0603, Power=65mW, Tolerance=1%
R108 R308: library part R0805_22R_1%, "Resistor, Thin Film, 22R, 1%, 125mW, 0805", CASE=0805, Power=125mW, Tolerance=1%
R111: library part R0603_1M_1%, "Resistor, Thin Film, 1M, 1%, 65mW, 0603", CASE=0603, Power=65mW, Tolerance=1%
R206 R207: library part Resistor, "Resistor"
R300: library part R0805_0R1_1%, "Resistor, Thin Film, 0R1, 1%, 125mW, 0805", CASE=0805, Power=125mW, Tolerance=1%
R301: library part R0603_33k_1%, "Resistor, Thin Film, 33k, 1%, 65mW, 0603", CASE=0603, Power=65mW, Tolerance=1%
R305 R307 R313: library part R0805_1k_1%, "Resistor, Thin Film, 1k, 1%, 125mW, 0805", CASE=0805, Power=125mW, Tolerance=1%
R306 R311: library part R0805_10k_1%, "Resistor, Thin Film, 10k, 1%, 125mW, 0805", CASE=0805, Power=125mW, Tolerance=1%
R309: library part R0805_3R3_1%, "Resistor, Thin Film, 3R3, 1%, 125mW, 0805", CASE=0805, Power=125mW, Tolerance=1%
S200: "Switch", Manufacturer_Name=Lorlin, Mouser Part Number=105-CK1049
U100: "Regulateur LDO 3.3V, 500mA", CASE=SOT-223
U200: "ARM Cortex-M0+ 32-bit MCU, 32 KB Flash, 8 KB Internal RAM, 20-pin TSSOP"

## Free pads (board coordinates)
  round 6 hole 6 unplated: 1(6,29) 1(6,61) 1(119,6) 1(119,61)

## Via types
v1: diameter 0.7, hole 0.35, Top Layer to Bottom Layer, 373 vias
v2: diameter 1.27, hole 0.711, Top Layer to Bottom Layer, tented both sides, 89 vias
v3: diameter 0.6, hole 0.3, Top Layer to Bottom Layer, tented both sides, 52 vias
v4: diameter 0.8, hole 0.35, Top Layer to Bottom Layer, 1 vias

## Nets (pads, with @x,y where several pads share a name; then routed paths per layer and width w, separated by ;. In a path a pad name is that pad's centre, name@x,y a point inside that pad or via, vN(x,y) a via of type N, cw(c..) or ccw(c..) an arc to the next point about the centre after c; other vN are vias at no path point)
3V3: C105.1 C200.1 C201.1 C202.1 C206.1 C207.2 C302.1 IC300.5 J200.1 J201.1 J203.1 J204.1 R201.2 R206.2 R207.2 U100.3 U200.4 | length 161.1
  Top Layer w0.3: J204.1@51.2,72.35 51.2,76 51.8,76.6 55.8,76.6 56.2,76.2 56.2,69.2 56.824,68.576 56.824,67.862 R206.2@56.762,67.8
  Top Layer w0.305: v3(38.6,41.1) C202.1@39.7,41.1 39.8,41 42.5,41 42.825,40.675 U200.4@44.35,40.675 ; v3(61.341,30.607) 61.337,30.603 60.404,30.603 C200.1@60.4,30.6 60.5,30.6 60.748,30.352 60.748,30.279 60.926,30.1 64.4,30.1 64.638,30.338 65.008,30.338 J200.1@65.1,30.43 ; C302.1@63.9,17.7 64.024,17.824 64.926,17.824 65.302,17.448 66.089,17.448 IC300.5@66.162,17.375
  Top Layer w0.635: U100.3@45.5,53.95 C105.1@45.5,50.3 v2(46.7,50.3) 51.238,54.838 R207.2@51.238,66.6 ; R207.2@51.2,66.6 J204.1@51.2,72.35 ; v3(54.7,26.5) 54.7,24 61,17.7 C302.1@63.9,17.7 ; R201.2@90.4,43.8 90.4,43.7 90.483,43.617 90.583,43.617 v3(91.8,42.4) ; v2(111,39) 111.172,39 111.372,39.2 C206.1@113.5,39.2 116.35,39.2 116.367,39.183 116.617,39.183 J203.1@116.7,39.1
  Bottom Layer w0.305: v3(61.341,30.607) 61.341,31.064 62.277,32 64.68,32 64.98,31.7 J201.1@65.1,31.7
  Bottom Layer w0.635: v3(63.7,42.2) 64.4,41.5 90.9,41.5 v3(91.8,42.4) ; v2(66.8,39.7) 67,39.5 110.328,39.5 110.828,39 v2(111,39)
12V: C101.1 C104.1 C107.1 C308.1 IC102.1 IC103.2 IC301.7 L100.1 R102.2 U100.1 | length 170.8
  Top Layer w0.635: R102.2@19,73.8 v3(20.3,73.8) ; C101.1@31.9,61.45 v3(31.9,63.7) ; U100.1@40.9,53.169 40.9,53.1 41.1,52.9 C104.1@41.1,50.3 ; IC103.2@53.65,10.8 55.2,10.8 55.717,10.283 55.717,10.183 55.8,10.1 C107.1@55.9,10.1 57.6,10.1 58.2,10.7 v3(58.2,11) ; IC102.1@53.7,13.9 53.965,13.9 54.465,13.4 v3(55.1,13.4) ; IC301.7@93.012,17.635 v3(94.025,17.635) 94.835,17.635 95,17.8 C308.1@95.1,17.8
  Top Layer w1.27: L100.1@32.1,69.3 32.102,69.298 34.102,69.298 35,68.4 35,62.2 33.965,61.165 32.96,61.165 33.29,60.835 33.29,60.39 36.8,56.88 39.313,54.367 40.765,54.367 40.9,54.232 U100.1@40.9,53.95 ; C101.1@32.35,61 32.35,46.95 34.2,45.1 34.2,25 36.5,22.7 43.3,22.7 v2(47,19)
  Bottom Layer w0.635: v3(20.3,73.8) 20.3,69.225 25.825,63.7 v3(31.9,63.7) ; 54.9,19 55.1,18.8 v3(55.1,13.4) ; v3(58.2,11) 58.2,19
  Bottom Layer w1.27: v2(47,19) 54.9,19 58.2,19 92.66,19 v3(94.025,17.635)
